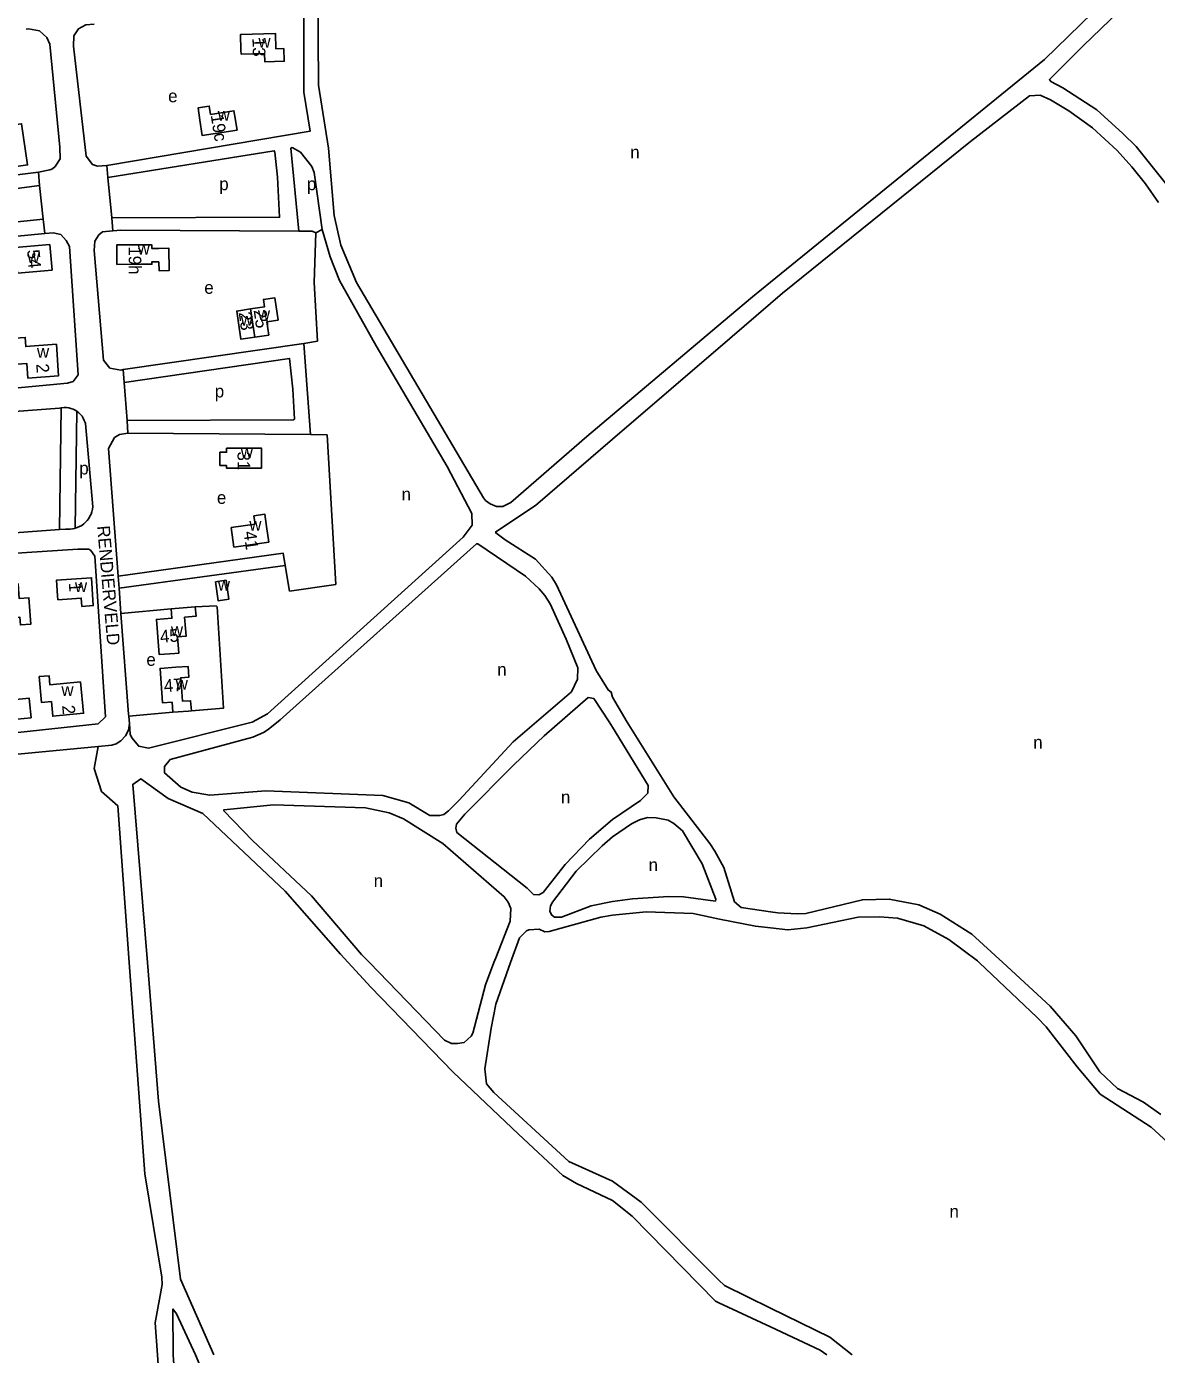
# Model space of a CAD drawing. Extents: x 162667 to 164645, y 379003 to 382150.
# Drawn here: x 163114.4 to 163472.3, y 380100.2 to 380520.8 of the extents above; entities that cross this region are included whole.
import ezdxf

# ---------------------------------------------------------------- set-up
doc = ezdxf.new("R2010")
doc.units = 0
for name, color, linetype in [('BLT_Basislijn', 7, 'Continuous'), ('BLT_Bebouwing', 7, 'Continuous'), ('BLT_Centroide', 7, 'Continuous'), ('BLT_Huisnummer', 7, 'Continuous'), ('BLT_Onderverdeling_panden', 7, 'Continuous'), ('BLT_Straatnaam_verkleind', 7, 'Continuous')]:
    doc.layers.add(name, color=color, linetype=linetype)

msp = doc.modelspace()

# ---------------------------------------------------------------- linework, layer by layer
at = {"layer": 'BLT_Basislijn'}
for p, q in [((163139.75, 380476.78), (163140.11, 380473.04)), ((163118.19, 380474.74), (163118.5, 380470.46)), ((163141.4, 380460.29), (163140.11, 380473.04)), ((163119.65, 380459.84), (163118.5, 380470.46)), ((163119.65, 380459.84), (163120.13, 380455.32)), ((163141.4, 380460.29), (163141.68, 380456.15)), ((163205.98, 380455.53), (163208.02, 380456.55)), ((163202.21, 380420.49), (163144.94, 380412.23)), ((163204.33, 380391.61), (163202.21, 380420.49)), ((163144.94, 380412.23), (163145.25, 380408.04)), ((163145.25, 380408.04), (163146.21, 380396.01)), ((163065.64, 380395.49), (163124.81, 380399.96)), ((163125.32, 380400.06), (163124.79, 380361.5)), ((163124.81, 380399.96), (163125.32, 380400.06)), ((163130.31, 380398.98), (163129.79, 380361.9)), ((163130.31, 380398.98), (163130.4, 380398.92)), ((163133.02, 380395.06), (163135.32, 380368.7)), ((163146.47, 380392.05), (163146.21, 380396.01)), ((163146.47, 380392.05), (163204.33, 380391.61)), ((163124.79, 380361.5), (163071.54, 380357.61)), ((163126.68, 380361.64), (163124.79, 380361.5)), ((163143.38, 380346.77), (163143.7, 380342.88)), ((163143.7, 380342.88), (163196.27, 380350.14)), ((163144.26, 380334.86), (163143.7, 380342.88)), ((163144.26, 380334.86), (163160.17, 380336.43)), ((163160.67, 380303.6), (163146.72, 380302.35)), ((162974.36, 380277.36), (163137.03, 380292.75)), ((163146.08, 380234.57), (163146.85, 380224.32)), ((163262.41, 380224.32), (163263, 380225.84))]:
    msp.add_line(p, q, dxfattribs=at)
for points in [[(163350, 380545.3), (163351.7, 380544.62), (163365.24, 380544.87), (163373.43, 380542.91), (163392.97, 380540.93), (163405.46, 380543), (163410.14, 380543.03), (163435.57, 380537.02), (163440.19, 380536.86), (163443.09, 380537.66), (163446.18, 380538.93), (163455.85, 380545.87), (163472.21, 380553.84), (163494.74, 380577.45), (163495.06, 380577.41), (163495.42, 380576.47), (163495.26, 380574.14), (163494.2, 380572.29), (163476.51, 380548.65), (163470.94, 380543.65), (163436.84, 380510.41), (163350, 380439.86)], [(163475.56, 380470.67), (163465.84, 380482.85), (163461.65, 380487.01), (163453.35, 380494.42), (163442.61, 380501.41), (163438.79, 380503.48), (163438.37, 380504.04), (163449.15, 380514.82), (163482.41, 380546.9)], [(163206.63, 380532.65), (163206.87, 380502.27), (163209.98, 380482.3), (163211.84, 380460.95), (163213.96, 380451.61), (163218.92, 380439.8), (163259.12, 380371.54), (163259.76, 380370.66), (163261.21, 380369.62), (163263.2, 380368.76), (163265.18, 380368.81), (163267.73, 380370.11), (163291.8, 380390.94), (163300, 380397.83), (163337, 380429.07)], [(163139.75, 380476.78), (163204.19, 380487.67), (163202.17, 380500.07), (163202.23, 380523.49)], [(163118.19, 380474.74), (163121.71, 380475.41), (163122.59, 380475.74), (163123.43, 380476.5), (163125.01, 380478.91), (163124.9, 380482.64), (163121.7, 380515.28), (163120.81, 380517.34), (163118.52, 380519.46), (163114.97, 380520.1), (163114.22, 380519.98)], [(163135.75, 380521.6), (163133.17, 380521.37), (163130.8, 380520.08), (163129.35, 380517.93), (163129.19, 380514.65), (163133.2, 380479.74), (163135.24, 380477.14), (163136.88, 380476.63), (163139.75, 380476.78)], [(163472.92, 380465.13), (163468.81, 380470.97), (163464.46, 380476.43), (163459.78, 380481.58), (163451.96, 380488.77), (163444.53, 380494.14), (163438.75, 380497.6), (163435.41, 380499.15), (163432, 380498.94), (163413.36, 380484.42), (163353.84, 380436.37), (163350, 380433.07)], [(163141.4, 380460.29), (163194.49, 380460.42), (163193.85, 380473.18), (163193.06, 380481.07), (163192.82, 380481.5), (163140.11, 380473.04)], [(163208.02, 380456.55), (163205.52, 380474.65), (163204.72, 380476.49), (163201.12, 380481.09), (163198.51, 380482.52), (163198.03, 380482.3), (163200.58, 380456.02)], [(163051.12, 380459.17), (163066.03, 380460.79), (163066.79, 380462.19), (163082.75, 380470.28), (163118.19, 380474.74)], [(163119.65, 380459.84), (163078.67, 380455.61), (163076.22, 380455.61), (163071.98, 380456.96), (163071.57, 380460.37), (163081.86, 380465.63), (163118.5, 380470.46)], [(163046.59, 380453.42), (163046.68, 380450.22), (163047.8, 380446.69), (163052.16, 380441.44), (163053.5, 380438.32), (163058.63, 380404.49), (163060.09, 380402.37), (163061.72, 380401.83), (163065.7, 380402.08), (163127.31, 380407.86), (163129.12, 380408.45), (163130.75, 380410.56), (163127.96, 380451.16), (163126.96, 380453.09), (163125.22, 380454.92), (163122.75, 380455.49), (163120.13, 380455.32)], [(163141.68, 380456.15), (163138.43, 380455.85), (163137.22, 380454.83), (163135.96, 380452.86), (163135.8, 380449.87), (163138.75, 380415.17), (163140.76, 380412.66), (163144.18, 380412.02), (163144.94, 380412.23)], [(163200.58, 380456.02), (163144.21, 380456.34), (163141.68, 380456.15)], [(163208.02, 380456.55), (163210.54, 380447.93), (163213.52, 380440.38), (163225.14, 380419.7), (163247.59, 380381.43), (163255.44, 380366.58), (163255.5, 380362.93), (163252.62, 380359.05), (163190.64, 380303.12), (163185.85, 380300.48), (163153.01, 380292.24), (163149.89, 380292.86), (163147.67, 380295.53), (163147.24, 380296.65), (163146.93, 380300.1)], [(163200.58, 380456.02), (163204.83, 380456.02), (163205.98, 380455.53)], [(163202.21, 380420.49), (163206.49, 380421.16), (163205.47, 380439.75), (163205.98, 380455.53)], [(163046.59, 380453.42), (163066.82, 380455.46), (163067.52, 380453.57), (163077.97, 380451.15), (163120.13, 380455.32)], [(163337, 380429.07), (163344.28, 380435.22), (163350, 380439.86)], [(163337.13, 380422.02), (163350, 380433.07)], [(163338.57, 380243.54), (163335.2, 380254.39), (163332.36, 380259.61), (163330.77, 380262.07), (163319.36, 380276.79), (163304.61, 380300.48), (163300, 380308.44), (163299.5, 380309.98), (163298.64, 380310.69), (163294.83, 380316.82), (163282.23, 380343.98), (163280.8, 380346.36), (163275.57, 380352.11), (163265.94, 380358.24), (163263.01, 380360.45), (163262.98, 380360.81), (163275.63, 380369.16), (163300, 380390.14), (163337.13, 380422.02)], [(163146.21, 380396.01), (163198.92, 380396.3), (163199.24, 380396.5), (163198.69, 380405.93), (163197.68, 380415.72), (163145.25, 380408.04)], [(163125.32, 380400.06), (163125.53, 380400.1), (163126.26, 380400.17), (163127, 380400.15), (163127.72, 380400.06), (163128.43, 380399.88), (163129.12, 380399.63), (163129.78, 380399.31), (163130.31, 380398.98)], [(163130.4, 380398.92), (163130.97, 380398.46), (163131.49, 380397.94), (163131.95, 380397.37), (163132.35, 380396.75), (163132.67, 380396.09), (163132.93, 380395.41), (163133.02, 380395.06)], [(163143.38, 380346.77), (163140.37, 380387.2), (163142.19, 380390.63), (163143.84, 380391.6), (163146.47, 380392.05)], [(163196.27, 380350.14), (163197.68, 380341.99), (163212.29, 380344.1), (163209.55, 380391.49), (163204.33, 380391.61)], [(163135.32, 380368.7), (163135.22, 380367.92), (163135.04, 380367.15), (163134.79, 380366.41), (163134.45, 380365.7), (163134.05, 380365.02), (163133.58, 380364.39), (163133.05, 380363.81), (163132.47, 380363.29), (163131.83, 380362.83), (163131.15, 380362.43), (163130.43, 380362.11), (163129.79, 380361.9)], [(163129.79, 380361.9), (163129.69, 380361.86), (163128.92, 380361.69), (163128.14, 380361.6), (163127.36, 380361.59), (163126.68, 380361.64)], [(163031.8, 380290.09), (163111.62, 380297.18), (163137.07, 380299.97), (163139.39, 380302.17), (163135.99, 380353.06), (163134.7, 380354.91), (163134.07, 380355.23), (163130.66, 380355.33), (163027.2, 380348.5)], [(163285.24, 380326.74), (163288.97, 380317.72), (163288.92, 380314.09), (163286.95, 380310.04), (163268.53, 380294.2), (163251.35, 380275.72), (163248.05, 380272.39), (163246.55, 380271.27), (163245.29, 380270.95), (163242.07, 380270.9), (163235.48, 380274.92), (163227.19, 380277.24), (163190.11, 380278.73), (163172.37, 380277.3), (163166.86, 380278.33), (163163.19, 380279.92), (163158.11, 380284.38), (163158.03, 380286.45), (163159.88, 380288.68), (163186.08, 380295.7), (163189.47, 380297.2), (163190.92, 380298.18), (163194.69, 380301.2), (163256.91, 380356.94), (163257.31, 380356.94), (163272.44, 380346.74), (163276.71, 380342.76), (163278.57, 380340.62), (163280.25, 380337.93), (163285.24, 380326.74)], [(163143.38, 380346.77), (163195.67, 380353.98), (163196.27, 380350.14)], [(163144.26, 380334.86), (163146.66, 380303.04), (163146.72, 380302.35)], [(163167.82, 380337.04), (163174.38, 380337.29), (163174.7, 380336.97), (163176.79, 380304.95), (163166.59, 380304.03)], [(163299.95, 380298.87), (163298.89, 380300.62), (163294.02, 380307.97), (163292.21, 380308.32), (163278.36, 380296.18), (163268.73, 380286.98), (163253.15, 380271.33), (163250.58, 380268.14), (163250.36, 380266.85), (163250.68, 380265.48), (163272.92, 380247.86), (163274.91, 380245.9), (163276.67, 380245.82), (163277.96, 380246.52), (163284.98, 380255.41), (163292.67, 380263.38), (163300, 380269.67), (163308.83, 380275.69), (163311.14, 380278.03), (163311.3, 380280.36), (163299.95, 380298.87)], [(163146.93, 380300.1), (163146.61, 380297.9), (163145.74, 380296.11), (163144.19, 380294.54), (163142.78, 380293.56), (163141.4, 380293.17), (163137.03, 380292.75)], [(163146.93, 380300.1), (163146.72, 380302.35)], [(163146.08, 380234.57), (163143.27, 380274.02), (163138.14, 380278.5), (163135.75, 380285.75), (163137.03, 380292.75)], [(163152.63, 380224.32), (163148.02, 380280.74), (163150.54, 380282.53), (163159.21, 380276.26), (163170.22, 380271.58), (163196.28, 380246.93), (163213.82, 380226.96), (163216.25, 380224.32)], [(163263, 380225.84), (163267.51, 380237.47), (163267.79, 380241.41), (163266.89, 380243.47), (163265.66, 380245.17), (163246.25, 380262.01), (163233.72, 380269.88), (163229.18, 380271.7), (163221.68, 380273.31), (163192.55, 380274.27), (163176.88, 380272.71), (163176.85, 380272.4), (163185.92, 380263.03), (163204.63, 380245.46), (163220.5, 380226.86), (163222.95, 380224.32)], [(163305.99, 380268.26), (163300, 380264.12), (163296.72, 380261.33), (163288.45, 380253.24), (163280.96, 380243.42), (163280.36, 380242.34), (163280.1, 380240.58), (163280.64, 380239.41), (163281.59, 380238.73), (163283.76, 380238.65), (163293.23, 380242.28), (163300, 380243.7), (163306.27, 380244.52), (163317.83, 380245.23), (163322.45, 380245.15), (163332.58, 380243.81), (163332.74, 380244.45), (163328.41, 380255.57), (163322.13, 380266.1), (163319.36, 380268.42), (163317.61, 380269.46), (163313.84, 380270.15), (163311.04, 380270.32), (163308.53, 380269.54), (163305.99, 380268.26)], [(163350, 380240.42), (163340.71, 380241.77), (163338.57, 380243.54)], [(163350, 380240.42), (163352.3, 380240.09), (163358.41, 380239.73), (163361.23, 380239.89), (163379.11, 380244.19), (163387.61, 380244.43), (163397.01, 380242.65), (163403.76, 380239.68), (163413.74, 380233.36), (163423.58, 380224.32)], [(163333.91, 380238.11), (163325.48, 380239.81), (163310.6, 380240.37), (163300, 380239.3), (163296.25, 380238.65), (163279.93, 380234.19), (163278.5, 380234.09), (163276.71, 380234.88), (163273.49, 380234.73), (163272.77, 380234.4), (163270.47, 380232.11), (163267.71, 380224.32)], [(163350, 380235.32), (163345.23, 380235.83), (163333.91, 380238.11)], [(163416.15, 380224.32), (163415.59, 380224.85), (163406.53, 380231.62), (163398.61, 380235.94), (163390.23, 380238.38), (163384.52, 380238.77), (163377.8, 380238.7), (163361.48, 380235.27), (163355.53, 380234.72), (163350, 380235.32)], [(163146.85, 380224.32), (163151.85, 380157.41), (163157.18, 380124.68), (163157.31, 380122.29), (163155.08, 380110.21), (163155.88, 380100), (163160.69, 380026.5), (163161.11, 380020.26)], [(163173.73, 380100), (163163.13, 380124.01), (163156.21, 380180.36), (163152.63, 380224.32)], [(163216.25, 380224.32), (163223.43, 380216.54), (163249.34, 380189.7), (163270.2, 380169.93), (163284.28, 380156.81), (163288.6, 380154.35), (163300, 380148.9), (163306.2, 380143.98), (163332.55, 380117.09), (163333.69, 380116.56)], [(163222.95, 380224.32), (163246.73, 380199.77), (163249.02, 380198.68), (163250.87, 380198.68), (163253.01, 380199.03), (163255.25, 380201.02), (163255.71, 380201.9), (163259.7, 380217.3), (163262.41, 380224.32)], [(163267.71, 380224.32), (163263.04, 380211.18), (163261.49, 380203.56), (163259.57, 380190.65), (163260.09, 380185.9), (163262.41, 380183.19), (163286.09, 380161.26), (163300, 380155.03), (163309.01, 380148.38), (163333.7, 380123.71)], [(163486.46, 380100), (163487.06, 380103.43), (163488.2, 380125.63), (163489.42, 380128.69), (163490.5, 380134.84), (163490.34, 380139.29), (163489.98, 380141.09), (163490.05, 380144.55), (163495.06, 380152.11), (163495.38, 380153.13), (163484.8, 380159.12), (163470.62, 380172.18), (163454.46, 380182.62), (163447.13, 380191.27), (163437.36, 380203.92), (163434.53, 380206.91), (163416.15, 380224.32)], [(163423.58, 380224.32), (163438.59, 380210.53), (163446.72, 380201.1), (163454.37, 380189.69), (163459.94, 380184.45), (163468.16, 380180.05), (163473.64, 380176.16)], [(163333.7, 380123.71), (163335.42, 380121.99), (163350, 380114.83)], [(163333.69, 380116.56), (163350, 380108.93)], [(163350, 380114.83), (163368.81, 380105.59), (163375.88, 380100)], [(163160.73, 380114.58), (163160.79, 380100), (163166.65, 380015.42), (163171.17, 379956.86), (163188.36, 379908.1), (163208.87, 379876.75), (163227.24, 379859.14), (163243.86, 379851.42), (163244.25, 379851.58), (163245.12, 379854.44), (163245.81, 379857.9), (163226.7, 379929.54), (163223.11, 379961.78), (163220.49, 379976.89), (163218.59, 379983.12), (163214.3, 379994.7), (163195.82, 380059.84), (163193.9, 380064.62), (163190.73, 380070.6), (163188.98, 380072.76), (163172.21, 380089.67), (163167.92, 380100), (163161.85, 380113.02), (163160.73, 380114.58)], [(163350, 380108.93), (163365.79, 380101.54), (163367.86, 380100)]]:
    msp.add_lwpolyline(points, dxfattribs=at)
at = {"layer": 'BLT_Bebouwing'}
for p, q in [((163175.6, 380386.01), (163175.62, 380381.75)), ((163180, 380355.96), (163179.13, 380362.15)), ((163160.17, 380336.43), (163167.82, 380337.04))]:
    msp.add_line(p, q, dxfattribs=at)
for points in [[(163193.36, 380513.81), (163195.86, 380513.88), (163195.97, 380509.87), (163189.81, 380509.7), (163189.73, 380512.31), (163182.32, 380512.11), (163182.29, 380513.35), (163182.15, 380518.35), (163193.22, 380518.65), (163193.36, 380513.81)], [(163180.25, 380493.01), (163180.06, 380494.19), (163172.68, 380493.01), (163172.25, 380495.67), (163168.75, 380495.11), (163169.23, 380491.24), (163170.03, 380486.31), (163181.04, 380488.07), (163180.25, 380493.01)], [(163108.3, 380476.07), (163114.72, 380477.02), (163112.79, 380490.08), (163106.37, 380489.14)], [(163156.31, 380446.34), (163154.08, 380446.32), (163154.06, 380445.55), (163150.54, 380445.52), (163143, 380445.48), (163142.96, 380451.68), (163154.02, 380451.74), (163154.03, 380450.56), (163156.28, 380450.57)], [(163156.28, 380450.57), (163159.44, 380450.59), (163159.49, 380443.52), (163156.33, 380443.5), (163156.31, 380446.34)], [(163194.04, 380427.81), (163193.01, 380434.94), (163189.37, 380434.4), (163189.72, 380432.02), (163185.35, 380431.38)], [(163186.66, 380422.46), (163182.26, 380421.81), (163180.94, 380430.73), (163185.35, 380431.38)], [(163194.04, 380427.81), (163190.45, 380427.27), (163191.07, 380423.11), (163186.66, 380422.46)], [(163175.62, 380381.75), (163177.71, 380381.76), (163177.71, 380380.94), (163188.83, 380380.98), (163188.83, 380382.28), (163188.81, 380387.28), (163177.73, 380387.24), (163177.73, 380386.01), (163175.6, 380386.01)], [(163179.13, 380362.15), (163186.75, 380363.22), (163186.38, 380365.84), (163189.86, 380366.33), (163190.4, 380362.46), (163191.09, 380357.51), (163180, 380355.96)], [(163131.91, 380337.14), (163135.51, 380337.39), (163134.98, 380346.25), (163123.87, 380345.47), (163124.22, 380340.49), (163124.31, 380339.26), (163131.72, 380339.78), (163131.91, 380337.14)], [(163174.18, 380344.93), (163177.57, 380345.41), (163178.4, 380339.42), (163175.02, 380338.95), (163174.18, 380344.93)], [(163160.17, 380336.43), (163160.41, 380333.41), (163155.49, 380333.02), (163156.38, 380321.87), (163161.36, 380322.27)], [(163161.36, 380322.27), (163162.62, 380322.37), (163162.22, 380327.47), (163164.89, 380327.68), (163164.69, 380330.18), (163164.42, 380333.73), (163168.06, 380334.02), (163167.82, 380337.04)], [(163160.67, 380303.6), (163160.44, 380306.8), (163157.46, 380306.58), (163156.66, 380317.53), (163161.65, 380317.9), (163165.56, 380318.11), (163165.8, 380314.75), (163163.23, 380314.56), (163163.78, 380307.08), (163166.35, 380307.26), (163166.59, 380304.03)], [(163115.32, 380306.87), (163115.2, 380308.05), (163107.81, 380307.32), (163107.55, 380309.91), (163104.15, 380309.57), (163104.4, 380307.05), (163103.97, 380307.01), (163104.1, 380305.76), (163104.59, 380300.78), (163115.81, 380301.89), (163115.32, 380306.87)], [(163166.59, 380304.03), (163165.66, 380303.97), (163160.67, 380303.6)]]:
    msp.add_lwpolyline(points, dxfattribs=at)
for points in [[(163122.43, 380443.71), (163111.46, 380442.76), (163110.74, 380450.83), (163121.71, 380451.8)], [(163110.76, 380422.13), (163113.96, 380422.35), (163114.14, 380419.46), (163123.83, 380420.19), (163124.54, 380410.22), (163114.78, 380409.48), (163114.43, 380414.13), (163111.34, 380413.91)], [(163101.91, 380343.64), (163111.68, 380344.31), (163112, 380339.67), (163115.11, 380339.88), (163115.69, 380331.51), (163112.44, 380331.29), (163112.27, 380333.71), (163102.64, 380333.05)], [(163118.33, 380314.89), (163121.51, 380315.2), (163121.79, 380312.3), (163131.45, 380313.25), (163132.42, 380303.29), (163122.66, 380302.35), (163122.22, 380306.99), (163119.12, 380306.69)]]:
    msp.add_lwpolyline(points, close=True, dxfattribs=at)
at = {"layer": 'BLT_Onderverdeling_panden'}
msp.add_line((163185.35, 380431.38), (163186.66, 380422.46), dxfattribs=at)

# ---------------------------------------------------------------- texts
at = {"layer": 'BLT_Centroide'}
for s, p in [('w', (163187.8, 380514.19)), ('e', (163159.22, 380496.86)), ('w', (163174.93, 380491)), ('n', (163305.59, 380479.05)), ('p', (163175.41, 380469.01)), ('p', (163203.17, 380469.01)), ('w', (163149.55, 380448.62)), ('w', (163114.62, 380445.89)), ('e', (163170.67, 380436.18)), ('w', (163187.64, 380427.89)), ('w', (163182.21, 380426.13)), ('w', (163117.67, 380415.91)), ('p', (163174, 380403.35)), ('w', (163182.21, 380384.09)), ('p', (163131.07, 380378.96)), ('e', (163174.67, 380369.63)), ('n', (163233.16, 380370.73)), ('w', (163184.92, 380361.16)), ('w', (163129.7, 380341.69)), ('w', (163174.96, 380342.17)), ('w', (163160.09, 380327.77)), ('e', (163152.33, 380318.33)), ('n', (163263.45, 380315.17)), ('w', (163161.62, 380310.8)), ('w', (163125.41, 380308.78)), ('n', (163433.24, 380292.1)), ('n', (163283.64, 380274.75)), ('n', (163311.41, 380253.28)), ('n', (163224.32, 380248.23)), ('n', (163406.71, 380143.47))]:
    msp.add_text(s, height=4, dxfattribs=at).set_placement(p)
at = {"layer": 'BLT_Huisnummer'}
for s, rotation, p in [('13', 271.5726, (163185.9, 380517.22)), ('19c', 279.1138, (163172.68, 380492.75)), ('54', 275.3247, (163114.49, 380450.02)), ('19h', 270.3328, (163146.7, 380451.22)), ('23', 277.9825, (163181.55, 380430.25)), ('25', 277.9825, (163186.29, 380430.95)), ('2', 274.2241, (163117.4, 380413.93)), ('31', 270.1948, (163181.19, 380386.22)), ('41', 277.9825, (163183.09, 380360.74)), ('1', 274.0146, (163127.74, 380344.59)), ('45', 4.5419, (163156.78, 380325.59)), ('47', 4.1649, (163158, 380309.99)), ('2', 275.5015, (163125.61, 380305.71))]:
    msp.add_text(s, height=4, rotation=rotation, dxfattribs=at).set_placement(p)
at = {"layer": 'BLT_Straatnaam_verkleind'}
msp.add_text('RENDIERVELD', height=4, rotation=274.9213, dxfattribs=at).set_placement((163136.71, 380362.59))

doc.saveas('drawing.dxf')
